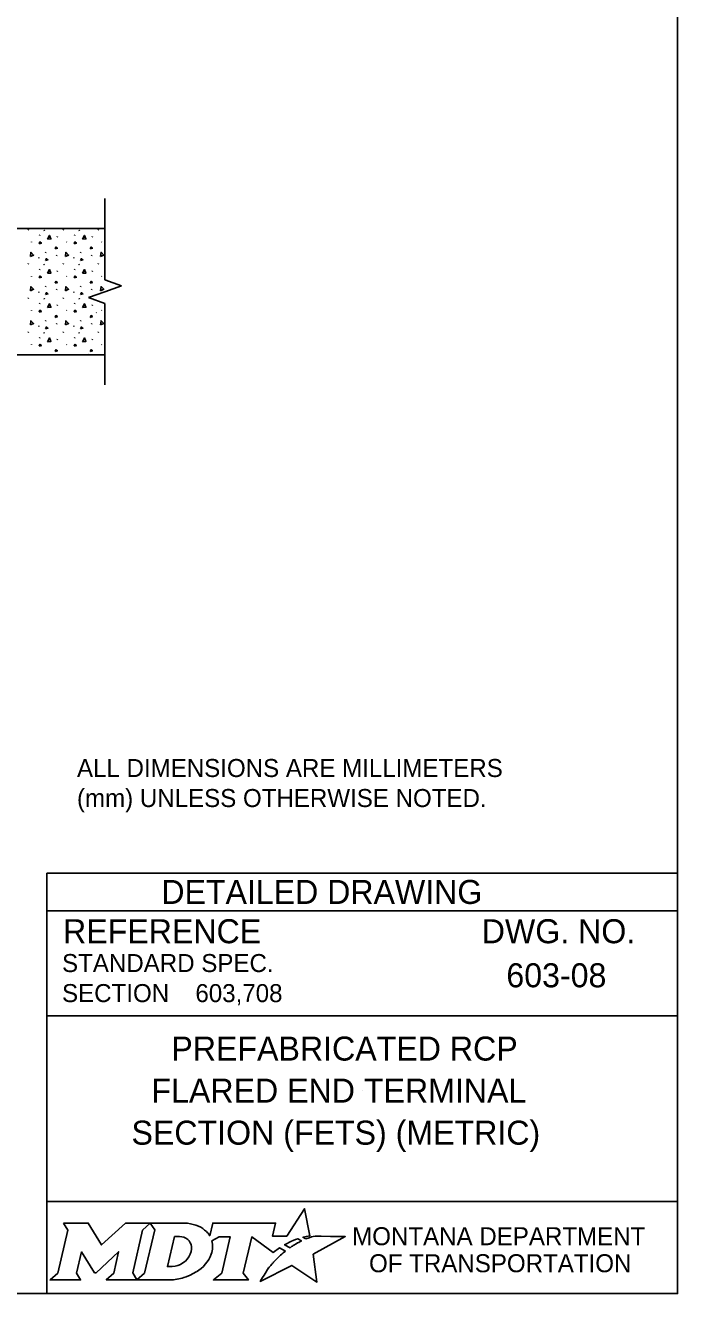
# Model space of a CAD drawing. Extents: x 49991.4 to 50022.1, y 49985 to 50011.4.
# Drawn here: x 50014.578 to 50016.75, y 49987.799 to 49992.021 of the extents above; entities that cross this region are included whole.
import ezdxf

# ---------------------------------------------------------------- set-up
doc = ezdxf.new("R2010")
doc.units = 0
for name, color, linetype in [('Default', 7, 'Continuous'), ('Level 1', 7, 'Continuous'), ('Level 2', 7, 'Continuous'), ('Level 5', 7, 'Continuous'), ('Level 6', 7, 'Continuous')]:
    doc.layers.add(name, color=color, linetype=linetype)

msp = doc.modelspace()

# ---------------------------------------------------------------- linework, layer by layer
at = {"layer": 'Default'}
for points in [[(50015.5126, 49987.9811), (50015.5023, 49987.9867), (50015.5139, 49987.9895), (50015.5255, 49987.9915), (50015.5081, 49988.0816), (50015.4486, 49987.9903), (50015.4013, 49987.9896), (50015.4116, 49988.0337), (50015.2024, 49988.0338), (50015.1923, 49987.9913), (50015.1865, 49987.9996)], [(50014.7056, 49988.0338), (50014.7197, 49988.0104), (50014.6862, 49987.8671), (50014.6605, 49987.8446), (50014.7621, 49987.8446), (50014.7486, 49987.8674), (50014.7648, 49987.9375), (50014.8085, 49987.8685), (50014.8138, 49987.8685), (50014.8889, 49987.938), (50014.8725, 49987.8669), (50014.8478, 49987.8449), (50014.9494, 49987.8449), (50014.9356, 49987.8682), (50014.9688, 49988.0106)], [(50014.9688, 49988.0106), (50014.9941, 49988.0338), (50014.9117, 49988.0338), (50014.8321, 49987.9608), (50014.7876, 49988.0335), (50014.7056, 49988.0338)], [(50015.1077, 49988.0338), (50014.9941, 49988.0338), (50015.0088, 49988.0109), (50014.9749, 49987.8671), (50014.9494, 49987.8449), (50015.06, 49987.8449)], [(50015.1317, 49987.9471), (50015.1305, 49987.939), (50015.1273, 49987.9297), (50015.1231, 49987.9215), (50015.1175, 49987.914), (50015.111, 49987.9071), (50015.1031, 49987.9008), (50015.0948, 49987.8961), (50015.0857, 49987.8922), (50015.0766, 49987.8899), (50015.0674, 49987.889), (50015.0515, 49987.889), (50015.0751, 49987.989), (50015.0911, 49987.989), (50015.0987, 49987.9884), (50015.1063, 49987.9865), (50015.1129, 49987.9835), (50015.119, 49987.9793), (50015.1238, 49987.9743), (50015.1275, 49987.9683), (50015.1302, 49987.9621), (50015.1318, 49987.9547), (50015.1318, 49987.9517), (50015.1317, 49987.9471)], [(50015.1991, 49987.9747), (50015.2237, 49987.9878), (50015.2606, 49987.9878), (50015.232, 49987.8673), (50015.2045, 49987.8446), (50015.3207, 49987.8446), (50015.3037, 49987.8675), (50015.3319, 49987.9877), (50015.4032, 49987.936), (50015.4243, 49987.9511), (50015.444, 49987.9402)], [(50015.3882, 49987.8843), (50015.3729, 49987.8599), (50015.3682, 49987.8524), (50015.3624, 49987.8438), (50015.3601, 49987.8395), (50015.4654, 49987.8926), (50015.5493, 49987.8375), (50015.5362, 49987.9302), (50015.6431, 49987.9886), (50015.5938, 49987.9894), (50015.5637, 49987.9898), (50015.5429, 49987.9901), (50015.5361, 49987.9886), (50015.5312, 49987.9874), (50015.5228, 49987.9851), (50015.5126, 49987.9811)], [(50015.4622, 49987.9535), (50015.4598, 49987.9518), (50015.4415, 49987.9614), (50015.4518, 49987.9671), (50015.4559, 49987.9693), (50015.4645, 49987.9733), (50015.4702, 49987.9759), (50015.4781, 49987.9789), (50015.4854, 49987.9816), (50015.4972, 49987.9742), (50015.4932, 49987.9721), (50015.4886, 49987.9696), (50015.4844, 49987.9674), (50015.4794, 49987.9645), (50015.4775, 49987.9634), (50015.4748, 49987.9618), (50015.4723, 49987.9604), (50015.47, 49987.9588), (50015.4674, 49987.957), (50015.4647, 49987.9552), (50015.4622, 49987.9535)], [(50015.4021, 49987.9004), (50015.4021, 49987.9004)], [(50015.1057, 49987.8522), (50015.1141, 49987.8548), (50015.1271, 49987.8602), (50015.1475, 49987.8712)]]:
    msp.add_lwpolyline(points, dxfattribs=at)
for centre, radius, start, end in [((50015.1308, 49987.9554), 0.0709, 339.5329, 15.8582), ((50015.0868, 49987.9727), 0.1183, 300.9103, 339.1383)]:
    msp.add_arc(centre, radius, start, end, dxfattribs=at)
for centre, major_axis, ratio, start_param, end_param in [((50015.1056, 49987.9864), (0.0834, -0.0037), 0.568097, 0.61298, 1.570796), ((50015.1612, 49987.9937), (0.0361, -0.0295), 0.469099, 1.225588, 1.570796), ((50015.4329, 49987.9305), (-0.0112, -0.0097), 0.021651, 3.157348, 6.283185), ((50015.3952, 49987.8923), (-0.00694, -0.00806), 0.008222, 0, 3.137361), ((50015.4119, 49987.9106), (-0.0098, -0.0102), 0.016458, 3.141593, 6.279097), ((50015.0603, 49987.9932), (0, 0.1484), 0.987302, 3.139398, 3.456847)]:
    msp.add_ellipse(centre, major_axis=major_axis, ratio=ratio, start_param=start_param, end_param=end_param, dxfattribs=at)
at = {"layer": 'Level 1'}
for p, q in [((50014.5274, 49991.3452), (50014.843, 49991.3452)), ((50014.5274, 49991.3452), (50014.843, 49991.3452)), ((50014.5875, 49991.3398), (50014.5884, 49991.342)), ((50014.6255, 49991.3217), (50014.6264, 49991.3239)), ((50014.6398, 49991.3398), (50014.6408, 49991.3383)), ((50014.6408, 49991.3392), (50014.6418, 49991.3378)), ((50014.6844, 49991.3161), (50014.6854, 49991.3183)), ((50014.7041, 49991.3398), (50014.7051, 49991.342)), ((50014.7422, 49991.3217), (50014.7431, 49991.3239)), ((50014.7565, 49991.3398), (50014.7575, 49991.3383)), ((50014.7575, 49991.3392), (50014.7585, 49991.3378)), ((50014.8011, 49991.3161), (50014.8021, 49991.3183)), ((50014.8208, 49991.3398), (50014.8218, 49991.342)), ((50014.5982, 49991.3005), (50014.5992, 49991.2991)), ((50014.645, 49991.2642), (50014.6459, 49991.2664)), ((50014.7149, 49991.3005), (50014.7158, 49991.2991)), ((50014.7616, 49991.2642), (50014.7626, 49991.2664)), ((50014.8316, 49991.3005), (50014.8325, 49991.2991)), ((50014.5875, 49991.226), (50014.5884, 49991.2282)), ((50014.6232, 49991.2481), (50014.6235, 49991.2459)), ((50014.6398, 49991.226), (50014.6408, 49991.2245)), ((50014.6408, 49991.2254), (50014.6418, 49991.224)), ((50014.682, 49991.2543), (50014.683, 49991.2564)), ((50014.7041, 49991.226), (50014.7051, 49991.2282)), ((50014.7399, 49991.2481), (50014.7401, 49991.2459)), ((50014.7565, 49991.226), (50014.7575, 49991.2245)), ((50014.7575, 49991.2254), (50014.7585, 49991.224)), ((50014.7987, 49991.2543), (50014.7996, 49991.2564)), ((50014.8208, 49991.226), (50014.8218, 49991.2282)), ((50014.5982, 49991.1868), (50014.5992, 49991.1853)), ((50014.6255, 49991.2079), (50014.6264, 49991.2101)), ((50014.6844, 49991.2023), (50014.6854, 49991.2045)), ((50014.7149, 49991.1868), (50014.7158, 49991.1853)), ((50014.7422, 49991.2079), (50014.7431, 49991.2101)), ((50014.8011, 49991.2023), (50014.8021, 49991.2045)), ((50014.8316, 49991.1868), (50014.8325, 49991.1853)), ((50014.645, 49991.1505), (50014.6459, 49991.1526)), ((50014.682, 49991.1405), (50014.683, 49991.1427)), ((50014.7616, 49991.1505), (50014.7626, 49991.1526)), ((50014.7987, 49991.1405), (50014.7996, 49991.1427)), ((50014.5875, 49991.1122), (50014.5884, 49991.1144)), ((50014.6232, 49991.1343), (50014.6235, 49991.1322)), ((50014.6398, 49991.1122), (50014.6408, 49991.1107)), ((50014.6408, 49991.1117), (50014.6418, 49991.1102)), ((50014.7041, 49991.1122), (50014.7051, 49991.1144)), ((50014.7399, 49991.1343), (50014.7401, 49991.1322)), ((50014.7565, 49991.1122), (50014.7575, 49991.1107)), ((50014.7575, 49991.1117), (50014.7585, 49991.1102)), ((50014.5982, 49991.073), (50014.5992, 49991.0715)), ((50014.6255, 49991.0942), (50014.6264, 49991.0963)), ((50014.6844, 49991.0885), (50014.6854, 49991.0907)), ((50014.7149, 49991.073), (50014.7158, 49991.0715)), ((50014.7422, 49991.0942), (50014.7431, 49991.0963)), ((50014.8011, 49991.0885), (50014.8021, 49991.0907)), ((50014.8143, 49991.0652), (50014.815, 49991.0642)), ((50014.8316, 49991.073), (50014.8325, 49991.0715)), ((50014.6232, 49991.0206), (50014.6235, 49991.0184)), ((50014.645, 49991.0367), (50014.6459, 49991.0389)), ((50014.682, 49991.0267), (50014.683, 49991.0289)), ((50014.7399, 49991.0206), (50014.7401, 49991.0184)), ((50014.7616, 49991.0367), (50014.7626, 49991.0389)), ((50014.7987, 49991.0267), (50014.7996, 49991.0289)), ((50014.5875, 49990.9984), (50014.5884, 49991.0006)), ((50014.6255, 49990.9804), (50014.6264, 49990.9826)), ((50014.6398, 49990.9984), (50014.6408, 49990.997)), ((50014.6408, 49990.9979), (50014.6418, 49990.9964)), ((50014.6844, 49990.9748), (50014.6854, 49990.9769)), ((50014.7041, 49990.9984), (50014.7051, 49991.0006)), ((50014.7422, 49990.9804), (50014.7431, 49990.9826)), ((50014.7565, 49990.9984), (50014.7575, 49990.997)), ((50014.7575, 49990.9979), (50014.7585, 49990.9964)), ((50014.8011, 49990.9748), (50014.8021, 49990.9769)), ((50014.8208, 49990.9984), (50014.8218, 49991.0006)), ((50014.5982, 49990.9592), (50014.5992, 49990.9577)), ((50014.7149, 49990.9592), (50014.7158, 49990.9577)), ((50014.8316, 49990.9592), (50014.8325, 49990.9577)), ((50014.843, 49990.9242), (50012.1908, 49990.9242)), ((50012.1908, 49990.9242), (50014.843, 49990.9242)), ((50014.6455, 49990.9242), (50014.6459, 49990.9251)), ((50014.7622, 49990.9242), (50014.7626, 49990.9251)), ((50014.7885, 49990.9255), (50014.7892, 49990.9271))]:
    msp.add_line(p, q, dxfattribs=at)
msp.add_lwpolyline([(49999.3835, 49998.9992), (50016.7501, 49998.9992), (50016.7501, 49987.7988), (49999.3835, 49987.7988)], close=True, dxfattribs=at)
for points in [[(50014.6515, 49991.3096), (50014.6581, 49991.322), (50014.6632, 49991.3105), (50014.6518, 49991.3096)], [(50014.7682, 49991.3096), (50014.7748, 49991.322), (50014.7799, 49991.3105), (50014.7685, 49991.3096)], [(50014.5949, 49991.2517), (50014.5969, 49991.2657), (50014.6056, 49991.2567), (50014.5952, 49991.2518)], [(50014.6238, 49991.2942), (50014.6267, 49991.3003), (50014.6316, 49991.2966), (50014.6238, 49991.2942)], [(50014.6772, 49991.2768), (50014.6801, 49991.2829), (50014.685, 49991.2792), (50014.6772, 49991.2768)], [(50014.7116, 49991.2517), (50014.7135, 49991.2657), (50014.7223, 49991.2567), (50014.7118, 49991.2518)], [(50014.7404, 49991.2942), (50014.7434, 49991.3003), (50014.7482, 49991.2966), (50014.7404, 49991.2942)], [(50014.7938, 49991.2768), (50014.7968, 49991.2829), (50014.8016, 49991.2792), (50014.7938, 49991.2768)], [(50014.8283, 49991.2517), (50014.8302, 49991.2657), (50014.839, 49991.2567), (50014.8285, 49991.2518)], [(50014.6454, 49991.2387), (50014.6484, 49991.2448), (50014.6532, 49991.2411), (50014.6454, 49991.2387)], [(50014.7621, 49991.2387), (50014.7651, 49991.2448), (50014.7699, 49991.2411), (50014.7621, 49991.2387)], [(50014.6238, 49991.1804), (50014.6267, 49991.1865), (50014.6316, 49991.1829), (50014.6238, 49991.1804)], [(50014.6515, 49991.1958), (50014.6581, 49991.2082), (50014.6632, 49991.1967), (50014.6518, 49991.1958)], [(50014.7404, 49991.1804), (50014.7434, 49991.1865), (50014.7482, 49991.1829), (50014.7404, 49991.1804)], [(50014.7682, 49991.1958), (50014.7748, 49991.2082), (50014.7799, 49991.1967), (50014.7685, 49991.1958)], [(50014.5949, 49991.1379), (50014.5969, 49991.1519), (50014.6056, 49991.1429), (50014.5952, 49991.138)], [(50014.6772, 49991.163), (50014.6801, 49991.1691), (50014.685, 49991.1654), (50014.6772, 49991.163)], [(50014.7116, 49991.1379), (50014.7135, 49991.1519), (50014.7223, 49991.1429), (50014.7118, 49991.138)], [(50014.7938, 49991.163), (50014.7968, 49991.1691), (50014.8016, 49991.1654), (50014.7938, 49991.163)], [(50014.8283, 49991.1379), (50014.8302, 49991.1519), (50014.839, 49991.1429), (50014.8285, 49991.138)], [(50014.6454, 49991.1249), (50014.6484, 49991.131), (50014.6532, 49991.1273), (50014.6454, 49991.1249)], [(50014.7621, 49991.1249), (50014.7651, 49991.131), (50014.7699, 49991.1273), (50014.7621, 49991.1249)], [(50014.6238, 49991.0666), (50014.6267, 49991.0727), (50014.6316, 49991.0691), (50014.6238, 49991.0666)], [(50014.6515, 49991.082), (50014.6581, 49991.0944), (50014.6632, 49991.0829), (50014.6518, 49991.082)], [(50014.6772, 49991.0492), (50014.6801, 49991.0553), (50014.685, 49991.0516), (50014.6772, 49991.0492)], [(50014.7404, 49991.0666), (50014.7434, 49991.0727), (50014.7482, 49991.0691), (50014.7404, 49991.0666)], [(50014.7682, 49991.082), (50014.7748, 49991.0944), (50014.7799, 49991.0829), (50014.7685, 49991.082)], [(50014.7938, 49991.0492), (50014.7968, 49991.0553), (50014.8016, 49991.0516), (50014.7938, 49991.0492)], [(50014.5949, 49991.0242), (50014.5969, 49991.0381), (50014.6056, 49991.0291), (50014.5952, 49991.0242)], [(50014.6454, 49991.0111), (50014.6484, 49991.0172), (50014.6532, 49991.0135), (50014.6454, 49991.0111)], [(50014.7116, 49991.0242), (50014.7135, 49991.0381), (50014.7223, 49991.0291), (50014.7118, 49991.0242)], [(50014.7621, 49991.0111), (50014.7651, 49991.0172), (50014.7699, 49991.0135), (50014.7621, 49991.0111)], [(50014.8283, 49991.0242), (50014.8302, 49991.0381), (50014.839, 49991.0291), (50014.8285, 49991.0242)], [(50014.6515, 49990.9682), (50014.6581, 49990.9806), (50014.6632, 49990.9692), (50014.6518, 49990.9682)], [(50014.7682, 49990.9682), (50014.7748, 49990.9806), (50014.7799, 49990.9692), (50014.7685, 49990.9682)], [(50014.6238, 49990.9528), (50014.6267, 49990.9589), (50014.6316, 49990.9553), (50014.6238, 49990.9528)], [(50014.6772, 49990.9354), (50014.6801, 49990.9415), (50014.685, 49990.9379), (50014.6772, 49990.9354)], [(50014.7404, 49990.9528), (50014.7434, 49990.9589), (50014.7482, 49990.9553), (50014.7404, 49990.9528)], [(50014.7938, 49990.9354), (50014.7968, 49990.9415), (50014.8016, 49990.9379), (50014.7938, 49990.9354)], [(50014.5969, 49990.9242), (50014.5969, 49990.9243), (50014.597, 49990.9242)], [(50014.7135, 49990.9242), (50014.7135, 49990.9243), (50014.7136, 49990.9242)], [(50014.8302, 49990.9242), (50014.8302, 49990.9243), (50014.8303, 49990.9242)]]:
    msp.add_lwpolyline(points, dxfattribs=at)
at = {"layer": 'Level 5'}
for p, q in [((50016.7501, 49989.1988), (50014.6501, 49989.1988)), ((50014.6501, 49989.1988), (50014.6501, 49987.7988)), ((50016.7501, 49989.0738), (50014.6501, 49989.0738)), ((50016.3862, 49988.8587), (50016.3862, 49988.8587)), ((50015.1444, 49988.7993), (50015.1444, 49988.7993)), ((50016.7501, 49988.7238), (50014.6501, 49988.7238)), ((50015.7001, 49988.4747), (50015.7001, 49988.4747)), ((50016.7501, 49988.1057), (50014.6501, 49988.1057))]:
    msp.add_line(p, q, dxfattribs=at)
at = {"layer": 'Level 6'}
for p, q in [((50014.843, 49991.4452), (50014.843, 49991.1736)), ((50014.8978, 49991.1541), (50014.843, 49991.1736)), ((50014.8978, 49991.1541), (50014.843, 49991.1347)), ((50014.843, 49991.1347), (50014.7882, 49991.1153)), ((50014.843, 49991.0958), (50014.7882, 49991.1153)), ((50014.843, 49991.0958), (50014.843, 49990.8242))]:
    msp.add_line(p, q, dxfattribs=at)

# ---------------------------------------------------------------- texts
at = {"layer": 'Default'}
for s, p in [('MONTANA DEPARTMENT', (50015.6663, 49987.96)), ('OF TRANSPORTATION', (50015.7225, 49987.87))]:
    msp.add_text(s, height=0.06, rotation=360, dxfattribs=at).set_placement(p)
at = {"layer": 'Level 2'}
for s, height, p in [('ALL DIMENSIONS ARE MILLIMETERS', 0.06, (50014.7501, 49989.5188)), ('(mm) UNLESS OTHERWISE NOTED.', 0.06, (50014.7501, 49989.4188)), ('603-08', 0.08, (50016.1798, 49988.8187)), ('603,708', 0.06, (50015.1444, 49988.7693)), ('PREFABRICATED RCP', 0.08, (50015.0644, 49988.5747)), ('FLARED END TERMINAL', 0.08, (50014.9981, 49988.4347)), ('SECTION (FETS) (METRIC)', 0.08, (50014.9316, 49988.2947))]:
    msp.add_text(s, height=height, dxfattribs=at).set_placement(p)
at = {"layer": 'Level 5'}
for s, height, p in [('DETAILED DRAWING', 0.0799, (50015.0311, 49989.0963)), ('REFERENCE', 0.08, (50014.7037, 49988.9654)), ('DWG. NO.', 0.08, (50016.0979, 49988.9654)), ('STANDARD SPEC.', 0.06, (50014.7004, 49988.8694)), ('SECTION', 0.06, (50014.7004, 49988.7694))]:
    msp.add_text(s, height=height, dxfattribs=at).set_placement(p)

doc.saveas('drawing.dxf')
